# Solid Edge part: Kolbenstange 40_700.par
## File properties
Username: ahadarics
Dokumentum tartalom típus: 0
Author: ahadarics
Last saved by: ahadarics
Revision: 95
Sűrűség: 0,000 kg/m^3
Pontosság: 0,990
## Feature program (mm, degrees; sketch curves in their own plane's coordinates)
base feature "unnamed BaseFeature 1"
thread "unnamed Thread 1"
chamfer "Letörés_1"  SetBackValue2 = 20 deg
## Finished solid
Body 1: solid body, 21 faces, 32 edges, 14 vertices.
  Faces by surface: plane 8, cylinder 5, cone 4, torus 4
  Edges by curve: circle 17, line 9, curve on surface 4, ellipse 2
Bounding box of the edges (mm; curved faces can reach further): 40.000 x 40.000 x 828.000, from (-20, -20, -78) to (20, 20, 750).
Cylindrical faces by radius (mm): R5 x1, R6 x1, R7.75 x1, R8 x1, R20 x1
Conical faces (half-angle, radius in mm at the cone's reference point): 20 deg R6 x1, 30 deg R7.875 x1, 45 deg R19.6 x1, 60 deg R5.5 x1
Toroidal faces (ring radius, tube radius in mm): R5.4 r0.4 x2, R6.55 r1.2 x2
Planar faces by outward normal: +x 1, +z 3, -x 1, -z 1, oblique 2
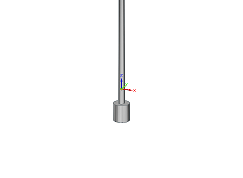
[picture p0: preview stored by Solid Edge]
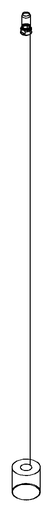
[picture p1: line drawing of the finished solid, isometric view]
